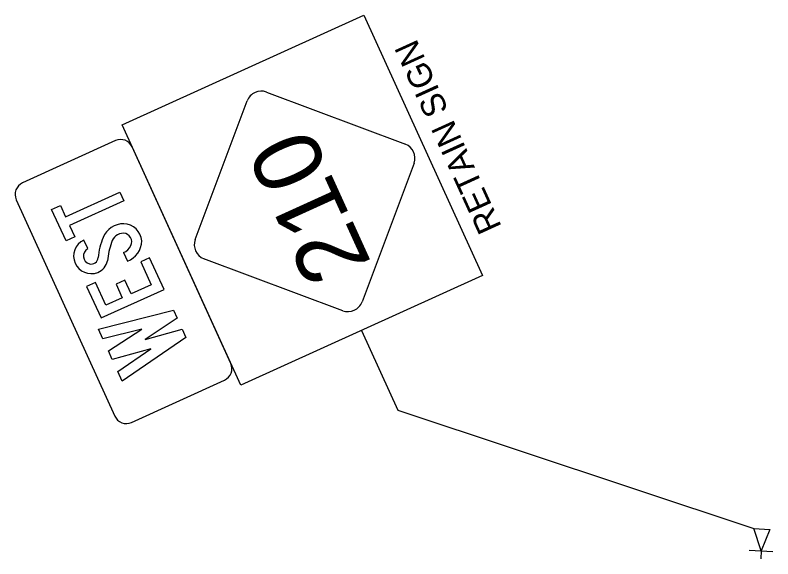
# Model space of a CAD drawing. Extents: x 2093420 to 2100301, y 676254 to 688367.
# Drawn here: x 2096491.7 to 2096709.9, y 684058.8 to 684215.4 of the extents above; entities that cross this region are included whole.
import ezdxf

# ---------------------------------------------------------------- set-up
doc = ezdxf.new("R2010")
doc.units = 0
for name, color, linetype in [('Default', 7, 'Continuous'), ('Exist Sign F 3 Digit NC Shield in Box CELL', 7, 'Continuous'), ('Exist Sign F West Panel CELL', 7, 'Continuous')]:
    doc.layers.add(name, color=color, linetype=linetype)

msp = doc.modelspace()

# ---------------------------------------------------------------- linework, layer by layer
at = {"layer": 'Default'}
for p, q in [((2096706.49, 684061.14), (2096704.41, 684067.55)), ((2096704.41, 684067.55), (2096708.97, 684067.31)), ((2096708.97, 684067.31), (2096706.49, 684061.14)), ((2096703.06, 684061.31), (2096709.86, 684060.96)), ((2096706.49, 684061.14), (2096706.37, 684058.83))]:
    msp.add_line(p, q, dxfattribs=at)
msp.add_lwpolyline([(2096591.45, 684124.63), (2096601.9, 684101.67), (2096704.41, 684067.55)], dxfattribs=at)
at = {"layer": 'Exist Sign F 3 Digit NC Shield in Box CELL'}
for p, q in [((2096564.09, 684193.29), (2096604.06, 684178.31)), ((2096543.57, 684150.79), (2096558.55, 684190.77)), ((2096606.58, 684172.77), (2096591.59, 684132.82)), ((2096586.05, 684130.3), (2096546.09, 684145.25))]:
    msp.add_line(p, q, dxfattribs=at)
msp.add_lwpolyline([(2096556.67, 684108.81), (2096522.57, 684183.79), (2096592.13, 684215.43), (2096626.24, 684140.45)], close=True, dxfattribs=at)
for centre, start, end in [((2096562.58, 684189.25), 69.458, 159.458), ((2096602.54, 684174.28), 339.458, 69.458), ((2096547.61, 684149.3), 159.458, 249.458), ((2096587.57, 684134.33), 249.458, 339.458)]:
    msp.add_arc(centre, 4.3, start, end, dxfattribs=at)
at = {"layer": 'Exist Sign F West Panel CELL'}
for p, q in [((2096520.59, 684179.28), (2096493.89, 684167.14)), ((2096553.79, 684115.14), (2096525.45, 684177.46)), ((2096492.06, 684162.28), (2096520.41, 684099.95)), ((2096512.65, 684148.17), (2096511.52, 684150.65)), ((2096512.65, 684148.17), (2096511.52, 684150.65)), ((2096512.65, 684148.17), (2096511.52, 684150.65)), ((2096522.92, 684147.04), (2096524.06, 684144.53)), ((2096522.92, 684147.04), (2096524.06, 684144.53)), ((2096522.92, 684147.04), (2096524.06, 684144.53)), ((2096525.27, 684098.14), (2096551.98, 684110.28))]:
    msp.add_line(p, q, dxfattribs=at)
for points in [[(2096507.41, 684154.83), (2096508.91, 684151.53), (2096506.38, 684150.38), (2096502.23, 684159.49), (2096504.77, 684160.64), (2096506.27, 684157.34), (2096521.87, 684164.43), (2096523.01, 684161.93)], [(2096507.41, 684154.83), (2096508.91, 684151.53), (2096506.38, 684150.38), (2096502.23, 684159.49), (2096504.77, 684160.64), (2096506.27, 684157.34), (2096521.87, 684164.43), (2096523.01, 684161.93)], [(2096507.41, 684154.83), (2096508.91, 684151.53), (2096506.38, 684150.38), (2096502.23, 684159.49), (2096504.77, 684160.64), (2096506.27, 684157.34), (2096521.87, 684164.43), (2096523.01, 684161.93)], [(2096530.92, 684137.79), (2096525.12, 684135.15), (2096523.34, 684139.07), (2096520.8, 684137.91), (2096522.58, 684134), (2096517.86, 684131.85), (2096514.86, 684138.46), (2096512.32, 684137.31), (2096516.46, 684128.2), (2096534.6, 684136.45), (2096530.45, 684145.56), (2096527.92, 684144.4)], [(2096530.92, 684137.79), (2096525.12, 684135.15), (2096523.34, 684139.07), (2096520.8, 684137.91), (2096522.58, 684134), (2096517.86, 684131.85), (2096514.86, 684138.46), (2096512.32, 684137.31), (2096516.46, 684128.2), (2096534.6, 684136.45), (2096530.45, 684145.56), (2096527.92, 684144.4)], [(2096530.92, 684137.79), (2096525.12, 684135.15), (2096523.34, 684139.07), (2096520.8, 684137.91), (2096522.58, 684134), (2096517.86, 684131.85), (2096514.86, 684138.46), (2096512.32, 684137.31), (2096516.46, 684128.2), (2096534.6, 684136.45), (2096530.45, 684145.56), (2096527.92, 684144.4)], [(2096530.76, 684119.34), (2096519.7, 684116.28), (2096518.59, 684118.7), (2096528.18, 684125.02), (2096517.02, 684122.16), (2096515.75, 684124.96), (2096537.31, 684130.49), (2096538.38, 684128.13), (2096529.12, 684122.02), (2096539.81, 684124.99), (2096540.88, 684122.63), (2096522.54, 684110.02), (2096521.27, 684112.82)], [(2096530.76, 684119.34), (2096519.7, 684116.28), (2096518.59, 684118.7), (2096528.18, 684125.02), (2096517.02, 684122.16), (2096515.75, 684124.96), (2096537.31, 684130.49), (2096538.38, 684128.13), (2096529.12, 684122.02), (2096539.81, 684124.99), (2096540.88, 684122.63), (2096522.54, 684110.02), (2096521.27, 684112.82)], [(2096530.76, 684119.34), (2096519.7, 684116.28), (2096518.59, 684118.7), (2096528.18, 684125.02), (2096517.02, 684122.16), (2096515.75, 684124.96), (2096537.31, 684130.49), (2096538.38, 684128.13), (2096529.12, 684122.02), (2096539.81, 684124.99), (2096540.88, 684122.63), (2096522.54, 684110.02), (2096521.27, 684112.82)]]:
    msp.add_lwpolyline(points, close=True, dxfattribs=at)
for centre, start, end in [((2096522.11, 684175.94), 24.458, 114.458), ((2096495.4, 684163.8), 114.458, 204.458), ((2096550.46, 684113.62), 294.458, 24.458), ((2096523.75, 684101.47), 204.458, 294.458)]:
    msp.add_arc(centre, 3.67, start, end, dxfattribs=at)
for centre, major_axis, start_param, end_param in [((2096522.8, 684149.26), (-5.62, -2.56), 4.260987, 5.485755), ((2096522.8, 684149.26), (-5.62, -2.56), 4.260987, 5.485755), ((2096522.8, 684149.26), (-5.62, -2.56), 4.260987, 5.485755), ((2096522.78, 684150), (-4.93, -2.24), 2.786047, 4.251692), ((2096522.78, 684150), (-4.93, -2.24), 2.786047, 4.251692), ((2096522.78, 684150), (-4.93, -2.24), 2.786047, 4.251692), ((2096534.63, 684144.33), (-17.4, -7.91), 5.462886, 5.782242), ((2096534.63, 684144.33), (-17.4, -7.91), 5.462886, 5.782242), ((2096534.63, 684144.33), (-17.4, -7.91), 5.462886, 5.782242), ((2096522.82, 684149.21), (-3.14, -1.43), 4.254409, 5.632398), ((2096522.82, 684149.21), (-3.14, -1.43), 4.254409, 5.632398), ((2096522.82, 684149.21), (-3.14, -1.43), 4.254409, 5.632398), ((2096522.79, 684150.12), (-2.3, -1.05), 2.261787, 4.23006), ((2096522.79, 684150.12), (-2.3, -1.05), 2.261787, 4.23006), ((2096522.79, 684150.12), (-2.3, -1.05), 2.261787, 4.23006), ((2096513.73, 684146.08), (-4.71, -2.14), 4.736267, 7.790596), ((2096513.73, 684146.08), (-4.71, -2.14), 4.736267, 7.790596), ((2096513.73, 684146.08), (-4.71, -2.14), 4.736267, 7.790596), ((2096538.38, 684143.43), (-18.37, -8.36), 5.515137, 5.786988), ((2096538.38, 684143.43), (-18.37, -8.36), 5.515137, 5.786988), ((2096538.38, 684143.43), (-18.37, -8.36), 5.515137, 5.786988), ((2096521.47, 684150.66), (-3.61, -1.64), 1.524757, 2.28214), ((2096521.47, 684150.66), (-3.61, -1.64), 1.524757, 2.28214), ((2096521.47, 684150.66), (-3.61, -1.64), 1.524757, 2.28214), ((2096521.68, 684150.46), (-5.93, -2.7), 1.526364, 2.701682), ((2096521.68, 684150.46), (-5.93, -2.7), 1.526364, 2.701682), ((2096521.68, 684150.46), (-5.93, -2.7), 1.526364, 2.701682), ((2096513.8, 684146.08), (-2.21, -1.01), 4.786904, 7.140738), ((2096513.8, 684146.08), (-2.21, -1.01), 4.786904, 7.140738), ((2096513.8, 684146.08), (-2.21, -1.01), 4.786904, 7.140738), ((2096513.64, 684145.69), (-1.82, -0.83), 0.87378, 2.656959), ((2096513.64, 684145.69), (-1.82, -0.83), 0.87378, 2.656959), ((2096513.64, 684145.69), (-1.82, -0.83), 0.87378, 2.656959), ((2096513.8, 684145.55), (-4.23, -1.92), 1.534831, 2.511766), ((2096513.8, 684145.55), (-4.23, -1.92), 1.534831, 2.511766), ((2096513.8, 684145.55), (-4.23, -1.92), 1.534831, 2.511766)]:
    msp.add_ellipse(centre, major_axis=major_axis, ratio=0.981173, start_param=start_param, end_param=end_param, dxfattribs=at)

# ---------------------------------------------------------------- texts
at = {"layer": 'Default'}
msp.add_text('RETAIN SIGN', height=7, rotation=114.4888, dxfattribs=at).set_placement((2096631.9, 684154.49))
at = {"layer": 'Exist Sign F 3 Digit NC Shield in Box CELL'}
msp.add_text('210', height=19.709, rotation=114.458, dxfattribs=at).set_placement((2096594.42, 684143.92))

doc.saveas('drawing.dxf')
